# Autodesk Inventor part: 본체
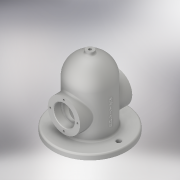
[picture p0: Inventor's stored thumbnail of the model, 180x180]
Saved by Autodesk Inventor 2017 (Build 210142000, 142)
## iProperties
Created: 2019-11
Part Number: 본체
Material: Aluminum 6061
Document SubType Name: Modeling
Designer: 1-19-lg
Density: 2.7 g/cm^3
Appearance: Aluminum - Flat
Mass: 1179.06 g
Surface Area: 919.015 cm^2
Volume: 436.69 cm^3
Author: 1-19-lg
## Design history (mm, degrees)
sketch "Sketch1"
  geometry: C1 r 70 at (0, 0); 1 further point
  constraints: 1 centre point, 1 coincident
  dimensions: "d0" = 140 diameter of C1
extrude "Extrusion1" new body sketch "Sketch1" distance "d1" = 10; taper "d2" = 0 deg
sketch "Sketch3"
  geometry: L1 (70, 10)-(-70, 10) reference; L2 (-70, 0)-(70, 0) reference; L3 (0, 10)-(-40, 10); L4 (-40, 10)-(-40, 90); L5 (0, -27.657)-(0, 165.941) reference; L6 (0, 130)-(0, 10); A1 r 40 centre (0, 90) between (0, 130) and (-40, 90); 1 further point
  constraints: 6 end point, 3 point on line, 2 point on circle, 1 centre point, 1 horizontal, 1 perpendicular
  dimensions: "d5" = 40 radius of A1; "d6" = 90 distance from line of L4.end L2
revolve "Revolution1" sketch "Sketch3" stored, may be unused: angle "d7" = 90 deg
sketch "Sketch4"
  geometry: C1 r 31 at (0, 50); 1 further point
  constraints: 1 centre point
  dimensions: "d8" = 62 diameter of C1; "d9" = 50 distance of C1.centre point (0, 0)
extrude "Extrusion2" join sketch "Sketch4" stored distance "d10" = 100; taper "d11" = 0 deg
sketch "Sketch5"
  geometry: C1 r 30 at (0, 0); 1 further point
  constraints: 1 centre point, 1 coincident
  dimensions: "d12" = 60 diameter of C1
extrude "Extrusion3" cut sketch "Sketch5" distance "d13" = 90; taper "d14" = 0 deg
sketch "Sketch6"
  geometry: C1 r 20 at (0, 0); 1 further point
  constraints: 1 centre point
  dimensions: "d15" = 40 diameter of C1
extrude "Extrusion4" cut sketch "Sketch6" distance "d16" = 15; taper "d17" = 0 deg
sketch "Sketch7"
  geometry: C1 r 20 at (0, 0); 1 further point
  constraints: 1 centre point
  dimensions: "d18" = 40 diameter of C1
extrude "Extrusion5" cut sketch "Sketch7" distance "d19" = 15; taper "d20" = 0 deg
sketch "Sketch8"
  geometry: C1 r 16.5 at (0, 0); C2 r 20 at (0, 0) reference; C3 r 31 at (0, 0) reference; 1 further point
  constraints: 1 centre point, 1 coincident
  dimensions: "d21" = 33 diameter of C1
extrude "Extrusion6" cut sketch "Sketch8" stored distance "d22" = 15; taper "d23" = 0 deg
sketch "Sketch14"
  geometry: L1 (30, 90)-(-30, 90) reference; L2 (0, 90)-(0, 120); L3 (0, 90)-(30, 90); L4 (40, 90)-(-40, 90) reference; A1 r 30 centre (0, 90) between (30, 90) and (0, 120); 1 further point
  constraints: 4 end point, 2 point on circle, 2 point on line, 1 centre point, 1 collinear, 1 midpoint, 1 vertical
revolve "Revolution2" sketch "Sketch14" stored, may be unused: angle "d56" = 90 deg
sketch "Sketch9"
  geometry: A1 r 26 centre (0, 0) between (0, 26) and (-26, 0); 3 further points
  constraints: 4 point on circle, 1 centre point
  dimensions: "d25" = 52 diameter of A1
hole "Hole1" sketch "Sketch9" at (0, 26), (-26, 0), (26, 0), (0, -26) diameter "d26" = 3.242; stored, may be unused: countersink angle "d30" = 90 deg, drill point angle "d32" = 118 deg; dims "d27" = 8, "d28" = 4, "d29" = 2, "d31" = 10
mirror "Mirror1"
sketch "Sketch10"
  geometry: C1 r 4.5 at (55, 0); C2 r 4.5 at (-55, 0); A1 r 55 centre (0, 0) between (55, 0) and (-55, 0); 1 further point
  constraints: 3 centre point, 2 point on circle, 1 coincident, 1 equal radius
  dimensions: "d33" = 110 diameter of A1; "d34" = 9 diameter of C2
extrude "Extrusion7" cut sketch "Sketch10" stored distance "d35" = 15; taper "d36" = 0 deg
workplane "Work Plane3"
sketch "Sketch12"
  geometry: C1 r 7.5 at (0, 0); 1 further point
  constraints: 1 centre point, 1 coincident
  dimensions: "d39" = 15 diameter of C1
extrude "Extrusion8" join sketch "Sketch12" stored distance "d40" = 15; taper "d41" = 0 deg
sketch "Sketch13"
  geometry: 2 further points
  constraints: 1 coincident
hole "Hole2" sketch "Sketch13" at (0, 0) diameter "d42" = 5.188; stored, may be unused: countersink angle "d46" = 90 deg, drill point angle "d48" = 118 deg; dims "d43" = 30, "d44" = 4, "d45" = 2, "d47" = 16
fillet "Fillet1" dims "d37" = 3, "d55" = 0.3
chamfer "Chamfer1" distance "d52" = 1; stored, may be unused: second distance "d53" = 2, angle "d54" = 45 deg
workplane "Work Plane1"
sketch "Sketch11"
  geometry: L1 (-15.847, 35.625)-(15.847, 35.625); L2 (15.847, 35.625)-(15.847, -34.965); L3 (15.847, -34.965)-(-15.847, -34.965); L4 (-15.847, -34.965)-(-15.847, 35.625); L5 (0, -76)-(0, 106) reference; L6 (-15.847, 0.33)-(15.847, 0.33); L7 (-70, -50)-(70, -50) reference; 1 further point
  constraints: 2 end point, 2 midpoint, 3 other
  dimensions: "d49" = 50.33 distance between parallel lines of L6 L7
emboss "Emboss1" sketch "Sketch11" dims "d12" = 60, "d50" = 0.5, "d51" = 0
body "Solid1"
node "Projected Loop1"
node "Projected Loop2"
other parameters: "d38" = 135
